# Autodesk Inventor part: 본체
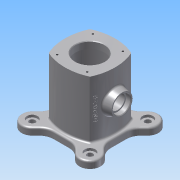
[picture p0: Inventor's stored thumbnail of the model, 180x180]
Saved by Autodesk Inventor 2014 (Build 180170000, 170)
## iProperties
Created: 2016-05
Part Number: 본체
Material: 알루미늄 6061
Document SubType Name: Modeling
Designer: 703-04
Density: 2.71 g/cm^3
Appearance: 알루미늄 - 평지
Mass: 1104.75 g
Surface Area: 865.47 cm^2
Volume: 407.655 cm^3
Author: 703-04
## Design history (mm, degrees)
sketch "스케치1"
  geometry: L1 (0, 70)-(0, -70); L2 (-49.497, 49.497)-(49.497, -49.497); L3 (49.497, -49.497)-(-49.497, 49.497); L4 (-56.322, 30.866)-(-62.225, 36.77); L5 (-36.77, 62.225)-(-30.866, 56.322); L6 (49.497, 49.497)-(-49.497, -49.497); L7 (-49.497, -49.497)-(49.497, 49.497); L8 (56.322, 30.866)-(62.225, 36.77); L9 (-56.322, -30.866)-(-62.225, -36.77); L10 (-49, 13.189)-(-49, -13.189); L11 (-49, -49)-(49, 49); L12 (48.999, -48.503)-(-49, 48.504); L13 (49, 13.189)-(49, -13.189); L14 (56.322, -30.866)-(62.225, -36.77); L15 (13.189, 49)-(-13.189, 49); L16 (-49, -49)-(49, 49); L17 (49, -49)-(-49, 49); L18 (36.77, 62.225)-(30.866, 56.322); L19 (-70, 0)-(70, 0); L20 (-36.77, -62.225)-(-30.866, -56.322); L21 (13.189, -49)-(-13.189, -49); L22 (36.77, -62.225)-(30.866, -56.322); A1 r 18 centre (49.497, -49.497) between (36.77, -62.225) and (62.225, -36.77); A2 r 18 centre (-49.497, 49.497) between (-36.77, 62.225) and (-62.225, 36.77); A3 r 18 centre (-49.497, -49.497) between (-62.225, -36.77) and (-36.77, -62.225); A4 r 18 centre (49.497, 49.497) between (62.225, 36.77) and (36.77, 62.225); A5 r 25 centre (-74, 13.189) between (-49, 13.189) and (-56.322, 30.866); A6 r 25 centre (-74, -13.189) between (-56.322, -30.866) and (-49, -13.189); A7 r 25 centre (-13.189, 74) between (-30.866, 56.322) and (-13.189, 49); A8 r 25 centre (74, 13.189) between (56.322, 30.866) and (49, 13.189); A9 r 25 centre (74, -13.189) between (49, -13.189) and (56.322, -30.866); A10 r 25 centre (13.189, 74) between (13.189, 49) and (30.866, 56.322); A11 r 25 centre (-13.189, -74) between (-13.189, -49) and (-30.866, -56.322); A12 r 25 centre (13.189, -74) between (30.866, -56.322) and (13.189, -49); 5 further points
  constraints: 48 end point, 24 point on circle, 14 symmetric about line, 14 tangent, 12 centre point, 10 midpoint, 8 point on line, 3 parallel, 1 coincident, 1 collinear, 1 equal radius, 1 perpendicular, 1 vertical, 1 vertical alignment, 5 other
  dimensions: "d1" = 45 deg angle of L1 L2; "d3" = 18 radius of A2; "d4" = 18 radius of A4; "d9" = 98 distance of L11.start L12.start; "d11" = 25 radius of A5; "d12" = 25 radius of A7; "d15" = 98 vertical distance of L6.start L12.start
extrude "돌출3" new body sketch "스케치1" distance "d16" = 12; taper "d17" = 0 deg
sketch "스케치2"
  geometry: A1 r 18 centre (49.497, -49.497) between (36.77, -62.225) and (62.225, -36.77) reference; A2 r 18 centre (49.497, 49.497) between (62.225, 36.77) and (36.77, 62.225) reference; A3 r 18 centre (-49.497, 49.497) between (-36.77, 62.225) and (-62.225, 36.77) reference; A4 r 18 centre (-49.497, -49.497) between (-62.225, -36.77) and (-36.77, -62.225) reference; 5 further points
  constraints: 4 coincident
hole "구멍1" sketch "스케치2" at (-49.497, 49.497), (49.497, 49.497), (49.497, -49.497), (-49.497, -49.497) diameter "d19" = 10; stored, may be unused: countersink angle "d23" = 90 deg, drill point angle "d25" = 118 deg; dims "d20" = 6, "d21" = 18, "d22" = 4, "d24" = 8
sketch "스케치3"
  geometry: L1 (-35.355, 35.355)-(35.355, 35.355); L2 (35.355, 35.355)-(35.355, -35.355); L3 (35.355, -35.355)-(-35.355, -35.355); L4 (-35.355, -35.355)-(-35.355, 35.355); L5 (-35.355, 35.355)-(35.355, -35.355); L6 (35.355, 35.355)-(-35.355, -35.355); L7 (43, 25.339)-(43, -26.671); L8 (-43, 22.756)-(-43, -22.756); L9 (-36.801, 43)-(36.801, 43); L10 (-36.801, -43)-(36.801, -43); A1 r 85.579 centre (42.579, 0) between (-35.355, 35.355) and (-35.355, -35.355); A2 r 85.579 centre (-42.579, 0) between (35.355, -35.355) and (35.355, 35.355); A3 r 85.579 centre (0, -42.579) between (35.355, 35.355) and (-35.355, 35.355); A4 r 85.579 centre (0, 42.579) between (-35.355, -35.355) and (35.355, -35.355); 10 further points
  constraints: 20 end point, 10 point on circle, 5 midpoint, 5 parallel, 4 centre point, 3 equal radius, 2 coincident, 2 perpendicular, 1 horizontal
  dimensions: "d51" = 100 distance of L1.end L3.end; "d58" = 43 distance from line of point (0, 0) L8; "d59" = 43 distance from line of L7 point (0, 0); "d60" = 43 distance from line of L9 point (0, 0); "d61" = 43 distance from line of point (0, 0) L10
extrude "돌출4" join sketch "스케치3" distance "d42" = 98; taper "d43" = 0 deg
sketch "스케치6"
  geometry: C1 r 25 at (0, 0); 1 further point
  constraints: 1 centre point, 1 coincident
  dimensions: "d62" = 50 diameter of C1
extrude "돌출6" cut sketch "스케치6" stored distance "d63" = 98; taper "d64" = 0 deg
node "작업 평면2"
sketch "스케치7"
  geometry: C1 r 35 at (0, 0); 1 further point
  constraints: 1 centre point, 1 coincident
  dimensions: "d66" = 70 diameter of C1
extrude "돌출7" cut sketch "스케치7" stored distance "d67" = 86; taper "d68" = 0 deg
node "작업 평면3"
sketch "스케치10"
  geometry: C1 r 20 at (0, 61); 1 further point
  constraints: 1 centre point, 1 vertical alignment
  dimensions: "d86" = 40 diameter of C1; "d87" = 61 distance of point (0, 0) C1.centre
extrude "돌출8" join sketch "스케치10" stored distance "d88" = 86; taper "d89" = 0 deg
sketch "스케치11"
  geometry: C1 r 20 at (0, 0) reference; 1 further point
hole "구멍4" sketch "스케치11" at (0, 0) diameter "d90" = 25; stored, may be unused: countersink angle "d94" = 90 deg, drill point angle "d96" = 118 deg; dims "d91" = 7, "d92" = 30, "d93" = 8, "d95" = 10
node "작업 평면4"
feature "면 기울기1" dims angle "d98" = 10 deg
node "작업 평면5"
sketch "스케치13"
  geometry: L1 (35.355, 110)-(-35.355, 110) reference; L2 (0, 0)-(0, 124.644); 1 further point
  constraints: 2 end point, 1 perpendicular, 1 other
  dimensions: "d101" = 29 distance from line of point (-29, 61) L2; "d111" = 49 distance from line of L1 point (-29, 61)
feature "엠보싱1" sketch "스케치13" dims "d102" = 0.5, "d103" = 0
fillet "모깎기1" dims "d104" = 3
fillet "모깎기2" dims "d105" = 3
fillet "모깎기3" dims "d106" = 3
fillet "모깎기4" dims "d107" = 3
chamfer "모따기1" distance "d108" = 1; stored, may be unused: second distance "d109" = 2, angle "d110" = 45 deg
sketch "스케치14" dims "d114" = 80
  geometry: L1 (-49, -13.189)-(-49, 13.189) reference; L2 (-28.284, 28.284)-(28.284, -28.284); L3 (0, 40)-(0, -40); L4 (0, -40)-(0, 40); L5 (28.284, 28.284)-(-28.284, -28.284); C1 r 25 at (0, 0) reference; C2 r 1.621 at (27.919, 28.645) reference; 7 further points
  constraints: 8 end point, 5 coincident, 4 midpoint, 1 parallel, 11 other
  dimensions: "d115" = 45 deg angle of L3 L2; "d116" = 45 deg angle of L5 L3
hole "구멍5" sketch "스케치14" at (-28.284, 28.284), (28.284, 28.284), (28.284, -28.284), (-28.284, -28.284) diameter "d117" = 3.242; stored, may be unused: countersink angle "d121" = 90 deg, drill point angle "d123" = 118 deg; dims "d118" = 7, "d119" = 4, "d120" = 2, "d122" = 10
sketch "스케치15"
  geometry: L1 (0, 40)-(0, -40); L2 (25.712, 30.642)-(-25.712, -30.642); L3 (-25.712, 30.642)-(25.712, -30.642); C1 r 26 at (0, 0) reference; A1 r 40 centre (0, 0) between (0, 40) and (0, -40); 5 further points
  constraints: 6 end point, 5 point on circle, 4 coincident, 2 midpoint, 2 symmetric about line, 1 centre point, 1 vertical
  dimensions: "d124" = 80 diameter of A1; "d125" = 40 deg angle of L2 L1
hole "구멍6" sketch "스케치15" at (-25.712, 30.642), (25.712, 30.642), (-25.712, -30.642), (25.712, -30.642) diameter "d126" = 3.242; stored, may be unused: countersink angle "d130" = 90 deg, drill point angle "d132" = 118 deg; dims "d127" = 7, "d128" = 4, "d129" = 2, "d131" = 10
fillet "모깎기5" dims "d133" = 3
node "솔리드2"
other parameters: "d65" = 55, "d85" = 55, "d97" = 43, "d99" = 43.5
